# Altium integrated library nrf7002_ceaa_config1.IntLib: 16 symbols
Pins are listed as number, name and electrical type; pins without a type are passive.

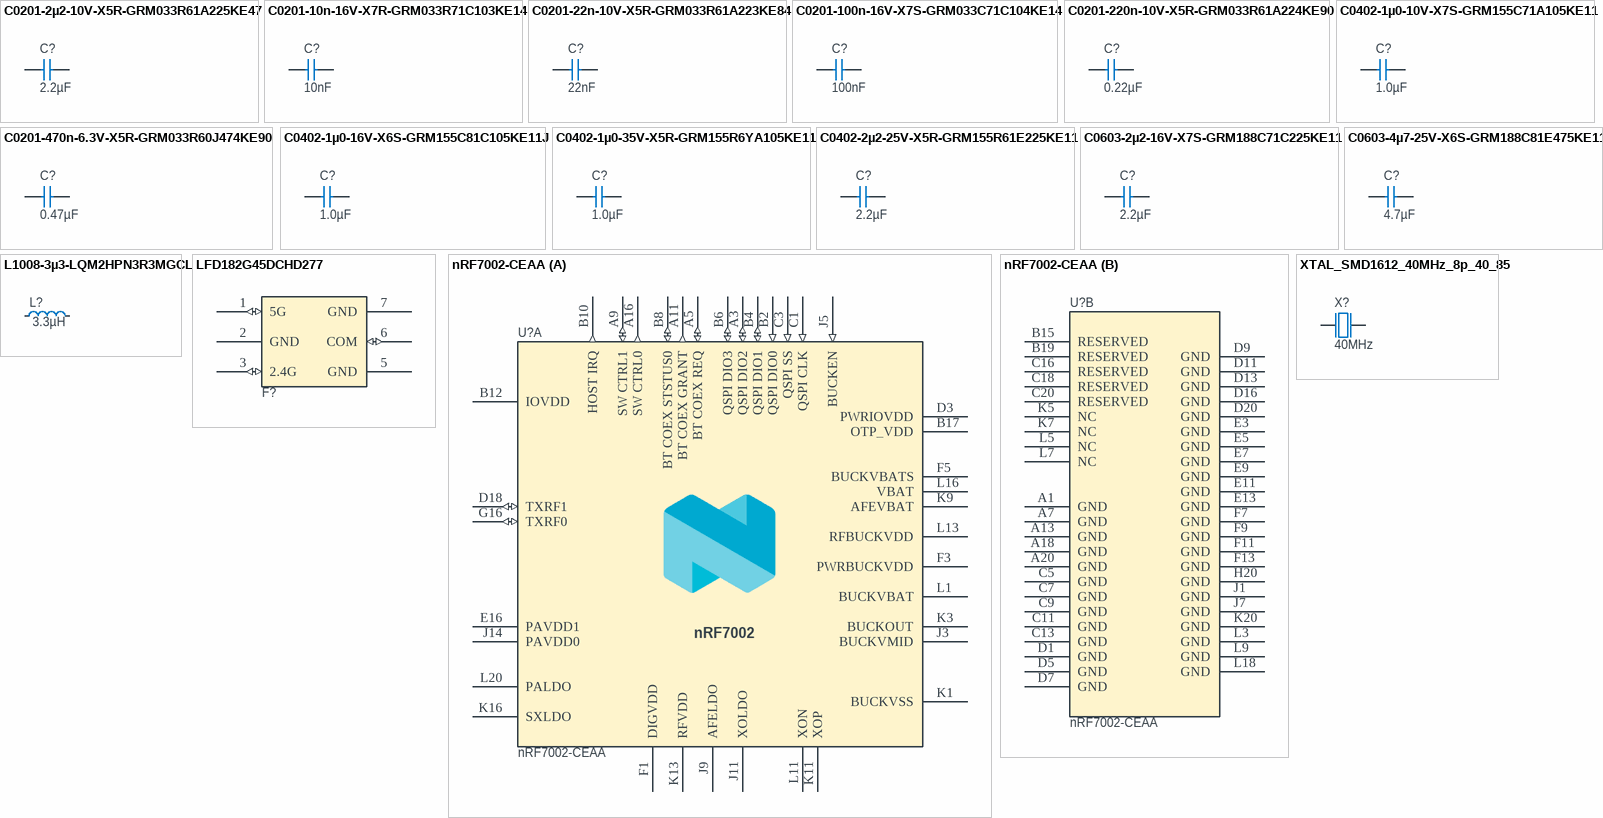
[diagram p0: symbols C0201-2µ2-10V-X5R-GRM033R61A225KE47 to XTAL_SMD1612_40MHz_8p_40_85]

## C0201-2µ2-10V-X5R-GRM033R61A225KE47
designator C?, comment 2.2µF
Capacitor, Ceramic, 2.2µF 10V X5R 0201,±10%; Part Number: C0201-2µ2-10V-X5R-GRM033R61A225KE47; Manufacturer: Murata; Manufacturer Part Number: GRM033R61A225KE47D; Pad Count: 2
footprint CAPC0603X03L_C
pins: 1, 2

## C0201-10n-16V-X7R-GRM033R71C103KE14
designator C?, comment 10nF
Capacitor, Ceramic, 10nF 16V X7R 0201,±10%; Part Number: C0201-10n-16V-X7R-GRM033R71C103KE14; Manufacturer: Murata; Manufacturer Part Number: GRM033R71C103KE14D; Pad Count: 2
footprint CAPC0603X03L_C
pins: 1, 2

## C0201-22n-10V-X5R-GRM033R61A223KE84
designator C?, comment 22nF
Capacitor, Ceramic, 22nF 10V X5R 0201,±10%; Part Number: C0201-22n-10V-X5R-GRM033R61A223KE84; Manufacturer: Murata; Manufacturer Part Number: GRM033R61A223KE84D; Pad Count: 2
footprint CAPC0603X03L_C
pins: 1, 2

## C0201-100n-16V-X7S-GRM033C71C104KE14
designator C?, comment 100nF
Capacitor, Ceramic, 100nF 16V X7S 0201,±10%; Part Number: C0201-100n-16V-X7S-GRM033C71C104KE14; Manufacturer: Murata; Manufacturer Part Number: GRM033C71C104KE14D; Pad Count: 2
footprint CAPC0603X03L_C
pins: 1, 2

## C0201-220n-10V-X5R-GRM033R61A224KE90
designator C?, comment 0.22µF
Capacitor, Ceramic, 0.22µF 10V X5R 0201, ±10%; Part Number: C0201-220n-10V-X5R-GRM033R61A224KE90; Manufacturer: Murata; Manufacturer Part Number: GRM033R61A224KE90D; Pad Count: 2
footprint CAPC0603X03L_C
pins: 1, 2

## C0201-470n-6.3V-X5R-GRM033R60J474KE90
designator C?, comment 0.47µF
Capacitor, Ceramic, 0.47µF 6.3V X5R 0201,±10%; Part Number: C0201-470n-6.3V-X5R-GRM033R60J474KE90; Manufacturer: Murata; Manufacturer Part Number: GRM033R60J474KE90D; Pad Count: 2
footprint CAPC0603X03L_C
pins: 1, 2

## C0402-1µ0-10V-X7S-GRM155C71A105KE11
designator C?, comment 1.0µF
Capacitor, Ceramic, 1.0µF 10V X7S 0402,±10%; Part Number: C0402-1µ0-10V-X7S-GRM155C71A105KE11; Manufacturer: Murata; Manufacturer Part Number: GRM155C71A105KE11D; Pad Count: 2
footprint CAPC1005X04L
pins: 1, 2

## C0402-1µ0-16V-X6S-GRM155C81C105KE11J
designator C?, comment 1.0µF
Capacitor, Ceramic, 1.0µF 16V X6S 0402,±10%; Part Number: C0402-1µ0-16V-X6S-GRM155C81C105KE11J; Manufacturer: Murata; Manufacturer Part Number: GRM155C81C105KE11J; Pad Count: 2
footprint CAPC1005X04L
pins: 1, 2

## C0402-1µ0-35V-X5R-GRM155R6YA105KE11
designator C?, comment 1.0µF
Capacitor, Ceramic, 1.0µF 35V X5R 0402,±10%; Part Number: C0402-1µ0-35V-X5R-GRM155R6YA105KE11; Manufacturer: Murata; Manufacturer Part Number: GRM155R6YA105KE11D; Pad Count: 2
footprint CAPC1005X04L
pins: 1, 2

## C0402-2µ2-25V-X5R-GRM155R61E225KE11
designator C?, comment 2.2µF
Capacitor, Ceramic, 2.2µF 25V X5R 0402,±10%; Part Number: C0402-2µ2-25V-X5R-GRM155R61E225KE11; Manufacturer: Murata; Manufacturer Part Number: GRM155R61E225KE11D; Pad Count: 2
footprint CAPC1005X04L
pins: 1, 2

## C0603-2µ2-16V-X7S-GRM188C71C225KE11
designator C?, comment 2.2µF
Capacitor, Ceramic, 2.2µF 16V X7S 0603,±10%; Part Number: C0603-2µ2-16V-X7S-GRM188C71C225KE11; Manufacturer: Murata; Manufacturer Part Number: GRM188C71C225KE11D; Pad Count: 2
footprint CAPC1608X06L
pins: 1, 2

## C0603-4µ7-25V-X6S-GRM188C81E475KE11
designator C?, comment 4.7µF
Capacitor, Ceramic, 4.7µF 25V X6S 0603,±10%; Part Number: C0603-4µ7-25V-X6S-GRM188C81E475KE11; Manufacturer: Murata; Manufacturer Part Number: GRM188C81E475KE11D; Pad Count: 2
footprint CAPC1608X06L
pins: 1, 2

## L1008-3µ3-LQM2HPN3R3MGCL
designator L?, comment 3.3µH
Inductor, 1A, ±20%, 200mOhm; Part Number: L1008-3µ3-LQM2HPN3R3MGCL; Manufacturer: Murata; Manufacturer Part Number: LQM2HPN3R3MGCL; Pad Count: 2
footprint INDC2520X10N
pins: 1, 2

## LFD182G45DCHD277
designator F?, comment LFD_5G_Diplexer  (value not drawn)
Signal Conditioning 2.4GHz and 5GHz Diplexer; Part Number: LFD182G45DCHD277; Manufacturer: Murata; Pad Count: 6; Value: LFD182G45DCHD277
footprint CAF-50P160X80-6N
pins: 1 5G (io), 2 GND (power), 3 2.4G (io), 5 GND (power), 6 COM (io), 7 GND (power)

## nRF7002-CEAA
designator U?
Wi-Fi Dual Band Companion chip WLCSP; Manufacturer: Nordic Semiconductor; Pad Count: 49
footprint nRF7002_WLCSP_R2
part A pins: A3 QSPI DIO2 (io), A5 BT COEX REQ (io), A9 SW CTRL1 (io), A11 BT COEX GRANT (out), A16 SW CTRL0 (out), B2 QSPI DIO0 (in), B4 QSPI DIO1 (io), B6 QSPI DIO3 (io), B8 BT COEX STSTUS0 (io), B10 HOST IRQ (out), B12 IOVDD, B17 OTP_VDD (power), C1 QSPI CLK (in), C3 QSPI SS (in), D3 PWRIOVDD (power), D18 TXRF1 (io), E16 PAVDD1 (power), F1 DIGVDD (power), F3 PWRBUCKVDD (power), F5 BUCKVBATS (power), G16 TXRF0 (io), J3 BUCKVMID (power), J5 BUCKEN (in), J9 AFELDO (power), J11 XOLDO (power), J14 PAVDD0 (power), K1 BUCKVSS (power), K3 BUCKOUT (power), K9 AFEVBAT (power), K11 XOP, K13 RFVDD (power), K16 SXLDO (power), L1 BUCKVBAT (power), L11 XON, L13 RFBUCKVDD (power), L16 VBAT (power), L20 PALDO (power)
part B pins: A1 GND (power), A7 GND (power), A13 GND (power), A18 GND (power), A20 GND (power), B15 RESERVED, B19 RESERVED, C5 GND (power), C7 GND (power), C9 GND (power), C11 GND (power), C13 GND (power), C16 RESERVED, C18 RESERVED, C20 RESERVED, D1 GND (power), D5 GND (power), D7 GND (power), D9 GND (power), D11 GND (power), D13 GND (power), D16 GND (power), D20 GND (power), E3 GND (power), E5 GND (power), E7 GND (power), E9 GND (power), E11 GND (power), E13 GND (power), F7 GND (power), F9 GND (power), F11 GND (power), F13 GND (power), H20 GND (power), J1 GND (power), J7 GND (power), K5 NC, K7 NC, K20 GND (power), L3 GND (power), L5 NC, L7 NC, L9 GND (power), L18 GND (power)

## XTAL_SMD1612_40MHz_8p_40_85
designator X?, comment 40MHz
XTAL SMD 1612, 40MHz, Cl=8pF, Total Tol: ±10ppm, -40-85C; Part Number: XTAL_SMD1612_40MHz_8p_40_85; Manufacturer: Abracon Corporation; Manufacturer Part Number: ABM12W-40.0000MHZ-8-D1X-T3; Pad Count: 4
footprint BT-XTAL_1612
pins: 1 inp, 2 GND hidden to GND, 3 out, 4 GND hidden to GND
